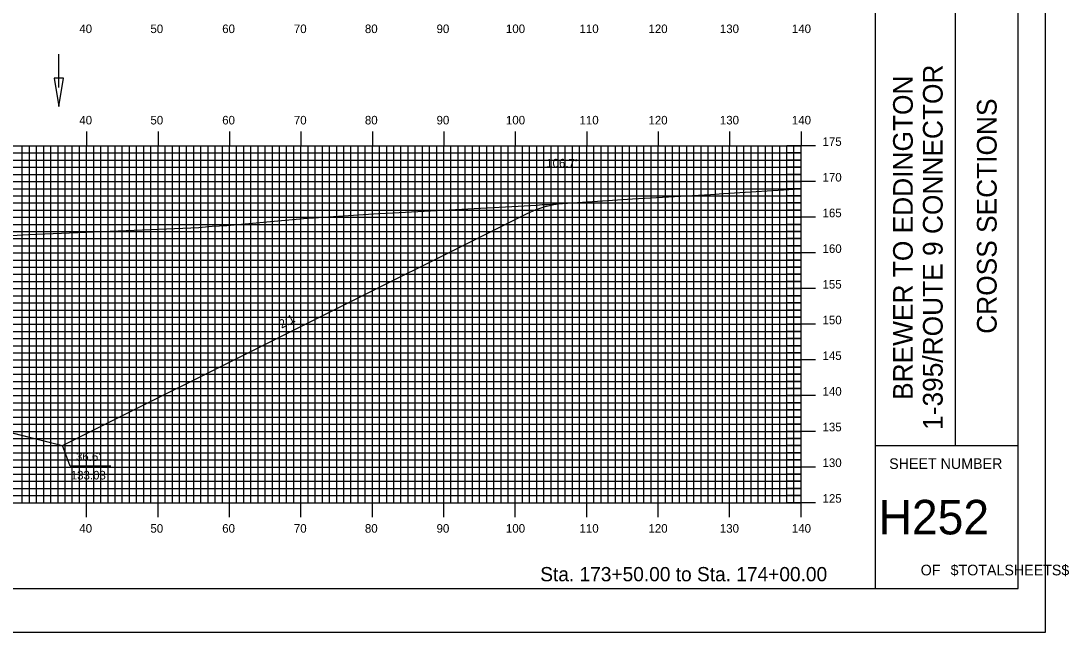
# Model space of a CAD drawing. Extents: x 1783434 to 1783777, y 442591 to 442811.
# Drawn here: x 1783630.8 to 1783777.5, y 442590.5 to 442676.2 of the extents above; entities that cross this region are included whole.
import ezdxf

# ---------------------------------------------------------------- set-up
doc = ezdxf.new("R2010")
doc.units = 0
for name, color, linetype in [('ANNOTATION', 7, 'Continuous'), ('BORDER', 7, 'Continuous'), ('D_Drainage_Ditch_Line', 7, 'Continuous'), ('D_Roadway_Centerline', 7, 'Continuous'), ('D_Roadway_SlopeLines', 7, 'Continuous'), ('D_Text_Standard', 7, 'Continuous'), ('H_V ANNOTATION', 7, 'Continuous'), ('MAJOR', 7, 'Continuous'), ('MINOR', 7, 'Continuous'), ('PLOT BOUNDARY', 7, 'Continuous'), ('S_Roadway_Centerline', 7, 'Continuous')]:
    doc.layers.add(name, color=color, linetype=linetype)

msp = doc.modelspace()

# ---------------------------------------------------------------- linework, layer by layer
at = {"layer": 'ANNOTATION'}
msp.add_lwpolyline([(1783643.38, 442613.81), (1783637.68, 442613.81), (1783636.61, 442616.7)], dxfattribs=at)
at = {"layer": 'BORDER'}
for p, q in [((1783750.37, 442596.67), (1783750.37, 442806.67)), ((1783761.56, 442616.67), (1783761.56, 442686.67)), ((1783761.56, 442616.67), (1783761.56, 442686.67)), ((1783750.37, 442616.67), (1783770.37, 442616.67)), ((1783750.37, 442616.67), (1783770.37, 442616.67))]:
    msp.add_line(p, q, dxfattribs=at)
msp.add_lwpolyline([(1783450.37, 442596.67), (1783770.37, 442596.67), (1783770.37, 442806.67), (1783450.37, 442806.67)], close=True, dxfattribs=at)
at = {"layer": 'D_Drainage_Ditch_Line'}
msp.add_line((1783636.08, 442666.83), (1783636.08, 442671.53), dxfattribs=at)
msp.add_lwpolyline([(1783636.74, 442668.14), (1783635.42, 442668.14), (1783636.08, 442664.2)], close=True, dxfattribs=at)
at = {"layer": 'D_Roadway_Centerline'}
msp.add_lwpolyline([(1783520.91, 442638.3), (1783522.16, 442638.29), (1783523.41, 442638.1), (1783524.66, 442637.74), (1783525.91, 442637.2), (1783565.8, 442617.26), (1783569.8, 442618.26), (1783579.97, 442620.8), (1783587.97, 442621.12), (1783599.97, 442621.36), (1783611.97, 442621.17), (1783619.97, 442620.85), (1783630.15, 442618.31), (1783636.61, 442616.7), (1783701.63, 442649.21), (1783702.88, 442649.76), (1783704.13, 442650.18), (1783705.38, 442650.47), (1783706.63, 442650.62)], dxfattribs=at)
at = {"layer": 'D_Roadway_SlopeLines'}
for points in [[(1783636.61, 442616.7), (1783701.63, 442649.21), (1783702.88, 442649.76), (1783704.13, 442650.18), (1783705.38, 442650.47), (1783706.63, 442650.62)], [(1783619.97, 442620.85), (1783636.61, 442616.7)]]:
    msp.add_lwpolyline(points, dxfattribs=at)
at = {"layer": 'MAJOR'}
for p, q in [((1783639.97, 442660.67), (1783639.97, 442658.67)), ((1783649.97, 442660.67), (1783649.97, 442658.67)), ((1783659.97, 442660.67), (1783659.97, 442658.67)), ((1783669.97, 442660.67), (1783669.97, 442658.67)), ((1783679.97, 442660.67), (1783679.97, 442658.67)), ((1783689.97, 442660.67), (1783689.97, 442658.67)), ((1783699.97, 442660.67), (1783699.97, 442658.67)), ((1783709.97, 442660.67), (1783709.97, 442658.67)), ((1783719.97, 442660.67), (1783719.97, 442658.67)), ((1783729.97, 442660.67), (1783729.97, 442658.67)), ((1783739.97, 442660.67), (1783739.97, 442658.67)), ((1783459.97, 442658.67), (1783739.97, 442658.67)), ((1783459.97, 442658.67), (1783739.97, 442658.67)), ((1783639.97, 442608.67), (1783639.97, 442658.67)), ((1783649.97, 442608.67), (1783649.97, 442658.67)), ((1783659.97, 442608.67), (1783659.97, 442658.67)), ((1783669.97, 442608.67), (1783669.97, 442658.67)), ((1783679.97, 442608.67), (1783679.97, 442658.67)), ((1783689.97, 442608.67), (1783689.97, 442658.67)), ((1783699.97, 442608.67), (1783699.97, 442658.67)), ((1783709.97, 442608.67), (1783709.97, 442658.67)), ((1783719.97, 442608.67), (1783719.97, 442658.67)), ((1783729.97, 442608.67), (1783729.97, 442658.67)), ((1783741.98, 442658.67), (1783737.97, 442658.67)), ((1783739.97, 442608.67), (1783739.97, 442658.67)), ((1783739.97, 442608.67), (1783739.97, 442658.67)), ((1783459.97, 442653.67), (1783739.97, 442653.67)), ((1783741.98, 442653.67), (1783737.97, 442653.67)), ((1783459.97, 442648.67), (1783739.97, 442648.67)), ((1783741.98, 442648.67), (1783737.97, 442648.67)), ((1783459.97, 442643.67), (1783739.97, 442643.67)), ((1783741.98, 442643.67), (1783737.97, 442643.67)), ((1783459.97, 442638.67), (1783739.97, 442638.67)), ((1783741.98, 442638.67), (1783737.97, 442638.67)), ((1783459.97, 442633.67), (1783739.97, 442633.67)), ((1783741.98, 442633.67), (1783737.97, 442633.67)), ((1783459.97, 442628.67), (1783739.97, 442628.67)), ((1783741.98, 442628.67), (1783737.97, 442628.67)), ((1783459.97, 442623.67), (1783739.97, 442623.67)), ((1783741.98, 442623.67), (1783737.97, 442623.67)), ((1783459.97, 442618.67), (1783739.97, 442618.67)), ((1783741.98, 442618.67), (1783737.97, 442618.67)), ((1783459.97, 442613.67), (1783739.97, 442613.67)), ((1783741.98, 442613.67), (1783737.97, 442613.67)), ((1783459.97, 442608.67), (1783739.97, 442608.67)), ((1783459.97, 442608.67), (1783739.97, 442608.67)), ((1783639.97, 442606.66), (1783639.97, 442608.67)), ((1783649.97, 442606.66), (1783649.97, 442608.67)), ((1783659.97, 442606.66), (1783659.97, 442608.67)), ((1783669.97, 442606.66), (1783669.97, 442608.67)), ((1783679.97, 442606.66), (1783679.97, 442608.67)), ((1783689.97, 442606.66), (1783689.97, 442608.67)), ((1783699.97, 442606.66), (1783699.97, 442608.67)), ((1783709.97, 442606.66), (1783709.97, 442608.67)), ((1783719.97, 442606.66), (1783719.97, 442608.67)), ((1783729.97, 442606.66), (1783729.97, 442608.67)), ((1783741.98, 442608.67), (1783737.97, 442608.67)), ((1783739.97, 442606.66), (1783739.97, 442608.67))]:
    msp.add_line(p, q, dxfattribs=at)
at = {"layer": 'MINOR'}
for p, q in [((1783630.97, 442608.67), (1783630.97, 442658.67)), ((1783631.97, 442608.67), (1783631.97, 442658.67)), ((1783632.97, 442608.67), (1783632.97, 442658.67)), ((1783633.97, 442608.67), (1783633.97, 442658.67)), ((1783634.97, 442608.67), (1783634.97, 442658.67)), ((1783635.97, 442608.67), (1783635.97, 442658.67)), ((1783636.97, 442608.67), (1783636.97, 442658.67)), ((1783637.97, 442608.67), (1783637.97, 442658.67)), ((1783638.97, 442608.67), (1783638.97, 442658.67)), ((1783640.97, 442608.67), (1783640.97, 442658.67)), ((1783641.97, 442608.67), (1783641.97, 442658.67)), ((1783642.97, 442608.67), (1783642.97, 442658.67)), ((1783643.97, 442608.67), (1783643.97, 442658.67)), ((1783644.97, 442608.67), (1783644.97, 442658.67)), ((1783645.97, 442608.67), (1783645.97, 442658.67)), ((1783646.97, 442608.67), (1783646.97, 442658.67)), ((1783647.97, 442608.67), (1783647.97, 442658.67)), ((1783648.97, 442608.67), (1783648.97, 442658.67)), ((1783650.97, 442608.67), (1783650.97, 442658.67)), ((1783651.97, 442608.67), (1783651.97, 442658.67)), ((1783652.97, 442608.67), (1783652.97, 442658.67)), ((1783653.97, 442608.67), (1783653.97, 442658.67)), ((1783654.97, 442608.67), (1783654.97, 442658.67)), ((1783655.97, 442608.67), (1783655.97, 442658.67)), ((1783656.97, 442608.67), (1783656.97, 442658.67)), ((1783657.97, 442608.67), (1783657.97, 442658.67)), ((1783658.97, 442608.67), (1783658.97, 442658.67)), ((1783660.97, 442608.67), (1783660.97, 442658.67)), ((1783661.97, 442608.67), (1783661.97, 442658.67)), ((1783662.97, 442608.67), (1783662.97, 442658.67)), ((1783663.97, 442608.67), (1783663.97, 442658.67)), ((1783664.97, 442608.67), (1783664.97, 442658.67)), ((1783665.97, 442608.67), (1783665.97, 442658.67)), ((1783666.97, 442608.67), (1783666.97, 442658.67)), ((1783667.97, 442608.67), (1783667.97, 442658.67)), ((1783668.97, 442608.67), (1783668.97, 442658.67)), ((1783670.97, 442608.67), (1783670.97, 442658.67)), ((1783671.97, 442608.67), (1783671.97, 442658.67)), ((1783672.97, 442608.67), (1783672.97, 442658.67)), ((1783673.97, 442608.67), (1783673.97, 442658.67)), ((1783674.97, 442608.67), (1783674.97, 442658.67)), ((1783675.97, 442608.67), (1783675.97, 442658.67)), ((1783676.97, 442608.67), (1783676.97, 442658.67)), ((1783677.97, 442608.67), (1783677.97, 442658.67)), ((1783678.97, 442608.67), (1783678.97, 442658.67)), ((1783680.97, 442608.67), (1783680.97, 442658.67)), ((1783681.97, 442608.67), (1783681.97, 442658.67)), ((1783682.97, 442608.67), (1783682.97, 442658.67)), ((1783683.97, 442608.67), (1783683.97, 442658.67)), ((1783684.97, 442608.67), (1783684.97, 442658.67)), ((1783685.97, 442608.67), (1783685.97, 442658.67)), ((1783686.97, 442608.67), (1783686.97, 442658.67)), ((1783687.97, 442608.67), (1783687.97, 442658.67)), ((1783688.97, 442608.67), (1783688.97, 442658.67)), ((1783690.97, 442608.67), (1783690.97, 442658.67)), ((1783691.97, 442608.67), (1783691.97, 442658.67)), ((1783692.97, 442608.67), (1783692.97, 442658.67)), ((1783693.97, 442608.67), (1783693.97, 442658.67)), ((1783694.97, 442608.67), (1783694.97, 442658.67)), ((1783695.97, 442608.67), (1783695.97, 442658.67)), ((1783696.97, 442608.67), (1783696.97, 442658.67)), ((1783697.97, 442608.67), (1783697.97, 442658.67)), ((1783698.97, 442608.67), (1783698.97, 442658.67)), ((1783700.97, 442608.67), (1783700.97, 442658.67)), ((1783701.97, 442608.67), (1783701.97, 442658.67)), ((1783702.97, 442608.67), (1783702.97, 442658.67)), ((1783703.97, 442608.67), (1783703.97, 442658.67)), ((1783704.97, 442608.67), (1783704.97, 442658.67)), ((1783705.97, 442608.67), (1783705.97, 442658.67)), ((1783706.97, 442608.67), (1783706.97, 442658.67)), ((1783707.97, 442608.67), (1783707.97, 442658.67)), ((1783708.97, 442608.67), (1783708.97, 442658.67)), ((1783710.97, 442608.67), (1783710.97, 442658.67)), ((1783711.97, 442608.67), (1783711.97, 442658.67)), ((1783712.97, 442608.67), (1783712.97, 442658.67)), ((1783713.97, 442608.67), (1783713.97, 442658.67)), ((1783714.97, 442608.67), (1783714.97, 442658.67)), ((1783715.97, 442608.67), (1783715.97, 442658.67)), ((1783716.97, 442608.67), (1783716.97, 442658.67)), ((1783717.97, 442608.67), (1783717.97, 442658.67)), ((1783718.97, 442608.67), (1783718.97, 442658.67)), ((1783720.97, 442608.67), (1783720.97, 442658.67)), ((1783721.97, 442608.67), (1783721.97, 442658.67)), ((1783722.97, 442608.67), (1783722.97, 442658.67)), ((1783723.97, 442608.67), (1783723.97, 442658.67)), ((1783724.97, 442608.67), (1783724.97, 442658.67)), ((1783725.97, 442608.67), (1783725.97, 442658.67)), ((1783726.97, 442608.67), (1783726.97, 442658.67)), ((1783727.97, 442608.67), (1783727.97, 442658.67)), ((1783728.97, 442608.67), (1783728.97, 442658.67)), ((1783730.97, 442608.67), (1783730.97, 442658.67)), ((1783731.97, 442608.67), (1783731.97, 442658.67)), ((1783732.97, 442608.67), (1783732.97, 442658.67)), ((1783733.97, 442608.67), (1783733.97, 442658.67)), ((1783734.97, 442608.67), (1783734.97, 442658.67)), ((1783735.97, 442608.67), (1783735.97, 442658.67)), ((1783736.97, 442608.67), (1783736.97, 442658.67)), ((1783737.97, 442608.67), (1783737.97, 442658.67)), ((1783738.97, 442608.67), (1783738.97, 442658.67)), ((1783459.97, 442657.67), (1783739.97, 442657.67)), ((1783739.97, 442657.67), (1783737.97, 442657.67)), ((1783459.97, 442656.67), (1783739.97, 442656.67)), ((1783459.97, 442655.67), (1783739.97, 442655.67)), ((1783739.97, 442656.67), (1783737.97, 442656.67)), ((1783739.97, 442655.67), (1783737.97, 442655.67)), ((1783459.97, 442654.67), (1783739.97, 442654.67)), ((1783739.97, 442654.67), (1783737.97, 442654.67)), ((1783459.97, 442652.67), (1783739.97, 442652.67)), ((1783739.97, 442652.67), (1783737.97, 442652.67)), ((1783459.97, 442651.67), (1783739.97, 442651.67)), ((1783739.97, 442651.67), (1783737.97, 442651.67)), ((1783459.97, 442650.67), (1783739.97, 442650.67)), ((1783459.97, 442649.67), (1783739.97, 442649.67)), ((1783739.97, 442650.67), (1783737.97, 442650.67)), ((1783739.97, 442649.67), (1783737.97, 442649.67)), ((1783459.97, 442647.67), (1783739.97, 442647.67)), ((1783459.97, 442646.67), (1783739.97, 442646.67)), ((1783739.97, 442647.67), (1783737.97, 442647.67)), ((1783739.97, 442646.67), (1783737.97, 442646.67)), ((1783459.97, 442645.67), (1783739.97, 442645.67)), ((1783739.97, 442645.67), (1783737.97, 442645.67)), ((1783459.97, 442644.67), (1783739.97, 442644.67)), ((1783739.97, 442644.67), (1783737.97, 442644.67)), ((1783459.97, 442642.67), (1783739.97, 442642.67)), ((1783739.97, 442642.67), (1783737.97, 442642.67)), ((1783459.97, 442641.67), (1783739.97, 442641.67)), ((1783459.97, 442640.67), (1783739.97, 442640.67)), ((1783739.97, 442641.67), (1783737.97, 442641.67)), ((1783739.97, 442640.67), (1783737.97, 442640.67)), ((1783459.97, 442639.67), (1783739.97, 442639.67)), ((1783739.97, 442639.67), (1783737.97, 442639.67)), ((1783459.97, 442637.67), (1783739.97, 442637.67)), ((1783739.97, 442637.67), (1783737.97, 442637.67)), ((1783459.97, 442636.67), (1783739.97, 442636.67)), ((1783739.97, 442636.67), (1783737.97, 442636.67)), ((1783459.97, 442635.67), (1783739.97, 442635.67)), ((1783739.97, 442635.67), (1783737.97, 442635.67)), ((1783459.97, 442634.67), (1783739.97, 442634.67)), ((1783739.97, 442634.67), (1783737.97, 442634.67)), ((1783459.97, 442632.67), (1783739.97, 442632.67)), ((1783739.97, 442632.67), (1783737.97, 442632.67)), ((1783459.97, 442631.67), (1783739.97, 442631.67)), ((1783459.97, 442630.67), (1783739.97, 442630.67)), ((1783739.97, 442631.67), (1783737.97, 442631.67)), ((1783739.97, 442630.67), (1783737.97, 442630.67)), ((1783459.97, 442629.67), (1783739.97, 442629.67)), ((1783739.97, 442629.67), (1783737.97, 442629.67)), ((1783459.97, 442627.67), (1783739.97, 442627.67)), ((1783739.97, 442627.67), (1783737.97, 442627.67)), ((1783459.97, 442626.67), (1783739.97, 442626.67)), ((1783739.97, 442626.67), (1783737.97, 442626.67)), ((1783459.97, 442625.67), (1783739.97, 442625.67)), ((1783459.97, 442624.67), (1783739.97, 442624.67)), ((1783739.97, 442625.67), (1783737.97, 442625.67)), ((1783739.97, 442624.67), (1783737.97, 442624.67)), ((1783459.97, 442622.67), (1783739.97, 442622.67)), ((1783459.97, 442621.67), (1783739.97, 442621.67)), ((1783739.97, 442622.67), (1783737.97, 442622.67)), ((1783739.97, 442621.67), (1783737.97, 442621.67)), ((1783459.97, 442620.67), (1783739.97, 442620.67)), ((1783739.97, 442620.67), (1783737.97, 442620.67)), ((1783459.97, 442619.67), (1783739.97, 442619.67)), ((1783739.97, 442619.67), (1783737.97, 442619.67)), ((1783459.97, 442617.67), (1783739.97, 442617.67)), ((1783739.97, 442617.67), (1783737.97, 442617.67)), ((1783459.97, 442616.67), (1783739.97, 442616.67)), ((1783459.97, 442615.67), (1783739.97, 442615.67)), ((1783739.97, 442616.67), (1783737.97, 442616.67)), ((1783739.97, 442615.67), (1783737.97, 442615.67)), ((1783459.97, 442614.67), (1783739.97, 442614.67)), ((1783739.97, 442614.67), (1783737.97, 442614.67)), ((1783459.97, 442612.67), (1783739.97, 442612.67)), ((1783459.97, 442611.67), (1783739.97, 442611.67)), ((1783739.97, 442612.67), (1783737.97, 442612.67)), ((1783739.97, 442611.67), (1783737.97, 442611.67)), ((1783459.97, 442610.67), (1783739.97, 442610.67)), ((1783739.97, 442610.67), (1783737.97, 442610.67)), ((1783459.97, 442609.67), (1783739.97, 442609.67)), ((1783739.97, 442609.67), (1783737.97, 442609.67))]:
    msp.add_line(p, q, dxfattribs=at)
at = {"layer": 'PLOT BOUNDARY'}
msp.add_lwpolyline([(1783434.19, 442590.55), (1783774.19, 442590.55), (1783774.19, 442810.55), (1783434.19, 442810.55)], close=True, dxfattribs=at)
at = {"layer": 'S_Roadway_Centerline'}
msp.add_lwpolyline([(1783615.82, 442645.3), (1783631.83, 442646.26), (1783638.76, 442646.52), (1783655.66, 442647.23), (1783657.53, 442647.4), (1783659.6, 442647.52), (1783670.34, 442648.5), (1783680.81, 442649.17), (1783682.81, 442649.27), (1783702.98, 442650.37), (1783703.74, 442650.44), (1783704.46, 442650.47), (1783716.38, 442651.27), (1783727.27, 442651.85), (1783729.13, 442651.98), (1783739.79, 442652.64), (1783739.97, 442652.65)], dxfattribs=at)

# ---------------------------------------------------------------- texts
at = {"layer": 'ANNOTATION'}
msp.add_text('2:1', height=1.2, rotation=26.5651, dxfattribs=at).set_placement((1783667.26, 442633.06))
for s, p in [("36.6'", (1783638.48, 442614.53)), ('133.03', (1783637.75, 442611.93))]:
    msp.add_text(s, height=1.2, dxfattribs=at).set_placement(p)
at = {"layer": 'BORDER'}
for s, p in [('1-395/ROUTE 9 CONNECTOR', (1783759.78, 442618.87)), ('BREWER TO EDDINGTON', (1783755.6, 442623.07)), ('CROSS SECTIONS', (1783767.34, 442632.34)), ('CROSS SECTIONS', (1783767.34, 442632.34))]:
    msp.add_text(s, height=2.7557, rotation=90, dxfattribs=at).set_placement(p)
for s, height, p in [('SHEET NUMBER', 1.4905, (1783752.3, 442613.4)), ('SHEET NUMBER', 1.4905, (1783752.3, 442613.4)), ('H252', 4.839, (1783750.81, 442604.23)), ('OF', 1.491, (1783756.71, 442598.49)), ('OF', 1.491, (1783756.71, 442598.49)), ('$TOTALSHEETS$', 1.4905, (1783760.89, 442598.49))]:
    msp.add_text(s, height=height, dxfattribs=at).set_placement(p)
at = {"layer": 'D_Text_Standard'}
msp.add_text("106.7'", height=1.2, dxfattribs=at).set_placement((1783704.3, 442655.65))
at = {"layer": 'H_V ANNOTATION'}
for s, height, p in [('40', 1.2, (1783638.95, 442674.47)), ('50', 1.2, (1783648.9, 442674.47)), ('60', 1.2, (1783658.95, 442674.47)), ('70', 1.2, (1783668.98, 442674.47)), ('80', 1.2, (1783678.92, 442674.47)), ('90', 1.2, (1783688.95, 442674.47)), ('100', 1.2, (1783698.66, 442674.47)), ('110', 1.2, (1783708.96, 442674.47)), ('120', 1.2, (1783718.61, 442674.47)), ('130', 1.2, (1783728.6, 442674.47)), ('140', 1.2, (1783738.68, 442674.47)), ('40', 1.2, (1783638.95, 442661.67)), ('50', 1.2, (1783648.9, 442661.67)), ('60', 1.2, (1783658.95, 442661.67)), ('70', 1.2, (1783668.98, 442661.67)), ('80', 1.2, (1783678.92, 442661.67)), ('90', 1.2, (1783688.95, 442661.67)), ('100', 1.2, (1783698.66, 442661.67)), ('110', 1.2, (1783708.96, 442661.67)), ('120', 1.2, (1783718.61, 442661.67)), ('130', 1.2, (1783728.6, 442661.67)), ('140', 1.2, (1783738.68, 442661.67)), ('175', 1.2, (1783742.97, 442658.67)), ('170', 1.2, (1783742.97, 442653.67)), ('165', 1.2, (1783742.97, 442648.67)), ('160', 1.2, (1783742.97, 442643.67)), ('155', 1.2, (1783742.97, 442638.67)), ('150', 1.2, (1783742.97, 442633.67)), ('145', 1.2, (1783742.97, 442628.67)), ('140', 1.2, (1783742.97, 442623.67)), ('135', 1.2, (1783742.97, 442618.67)), ('130', 1.2, (1783742.97, 442613.67)), ('125', 1.2, (1783742.97, 442608.67)), ('40', 1.2, (1783638.95, 442604.47)), ('50', 1.2, (1783648.9, 442604.47)), ('60', 1.2, (1783658.95, 442604.47)), ('70', 1.2, (1783668.98, 442604.47)), ('80', 1.2, (1783678.92, 442604.47)), ('90', 1.2, (1783688.95, 442604.47)), ('100', 1.2, (1783698.66, 442604.47)), ('110', 1.2, (1783708.96, 442604.47)), ('120', 1.2, (1783718.61, 442604.47)), ('130', 1.2, (1783728.6, 442604.47)), ('140', 1.2, (1783738.68, 442604.47)), ('Sta. 173+50.00 to Sta. 174+00.00', 2.0004, (1783703.46, 442597.66))]:
    msp.add_text(s, height=height, dxfattribs=at).set_placement(p)

doc.saveas('drawing.dxf')
